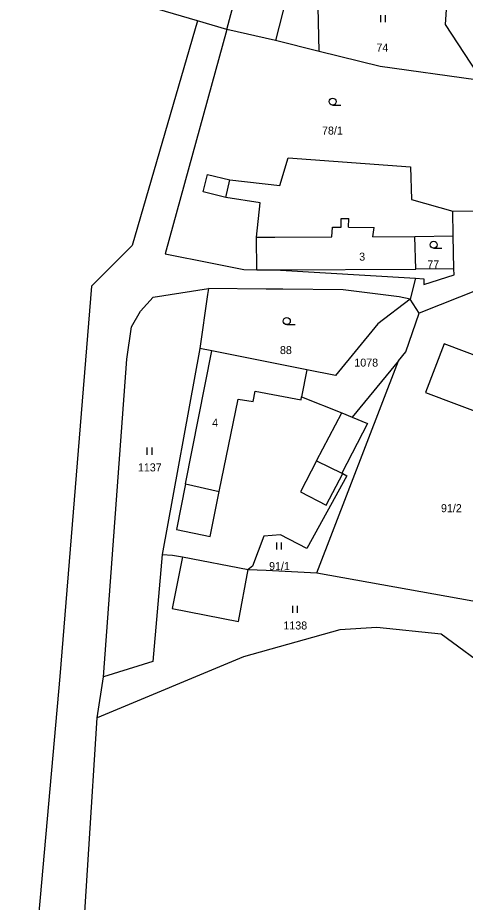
# Model space of a CAD drawing. Extents: x -746176 to -739709, y -1128407 to -1124482.
# Drawn here: x -742472.1 to -742377, y -1126240.2 to -1126052.3 of the extents above; entities that cross this region are included whole.
import ezdxf

# ---------------------------------------------------------------- set-up
doc = ezdxf.new("R2010")
doc.units = 0
for name, color, linetype in [('Hranice parcel', 7, 'Continuous'), ('Parcelní čísla', 7, 'Continuous'), ('Vnitřní kresba', 7, 'Continuous'), ('Značky kultur', 7, 'Continuous')]:
    doc.layers.add(name, color=color, linetype=linetype)

msp = doc.modelspace()

# ---------------------------------------------------------------- linework, layer by layer
at = {"layer": 'Hranice parcel'}
for p, q in [((-742410.68, -1126031.18), (-742417.35, -1126057.17)), ((-742433.87, -1126052.94), (-742452.02, -1126047.65)), ((-742427.68, -1126054.77), (-742433.87, -1126052.94)), ((-742417.35, -1126057.17), (-742427.68, -1126054.77)), ((-742408.01, -1126059.51), (-742417.35, -1126057.17)), ((-742379.56, -1126098.64), (-742379.6, -1126093.36)), ((-742379.39, -1126105.64), (-742379.56, -1126098.64)), ((-742387.54, -1126107.59), (-742388.7, -1126112.08)), ((-742386.77, -1126115.04), (-742388.7, -1126112.08)), ((-742389.6, -1126123.26), (-742386.77, -1126115.04)), ((-742433.38, -1126122.54), (-742441.38, -1126166.33)), ((-742391.19, -1126125.19), (-742389.6, -1126123.26)), ((-742408.55, -1126170.19), (-742391.19, -1126125.19)), ((-742391.19, -1126125.19), (-742401.05, -1126137.14)), ((-742408.55, -1126170.19), (-742366.28, -1126177.8)), ((-742455.22, -1126201.03), (-742453.88, -1126192.33))]:
    msp.add_line(p, q, dxfattribs=at)
for points in [[(-742427.68, -1126054.77), (-742421.67, -1126032.23), (-742472.11, -1126011.47)], [(-742408.01, -1126059.51), (-742408.36, -1126043.59), (-742380.73, -1126046.24)], [(-742380.73, -1126046.24), (-742381.25, -1126053.76), (-742374.55, -1126064.02)], [(-742433.87, -1126052.94), (-742447.8, -1126100.68), (-742456.41, -1126109.29), (-742463.16, -1126192.21), (-742472.54, -1126297.27), (-742476.24, -1126360.79), (-742482.39, -1126414.71)], [(-742427.68, -1126054.77), (-742440.74, -1126102.42), (-742430.76, -1126104.41), (-742424.03, -1126105.75), (-742421.29, -1126105.88)], [(-742374.74, -1126065.53), (-742395.07, -1126062.68), (-742408.01, -1126059.51)], [(-742421.29, -1126105.88), (-742421.35, -1126098.94), (-742420.61, -1126091.6), (-742427.91, -1126090.46), (-742432.7, -1126089.32), (-742431.8, -1126085.57), (-742427.02, -1126086.71), (-742416.37, -1126087.94), (-742414.61, -1126082.07), (-742388.6, -1126083.94), (-742388.43, -1126090.91), (-742379.6, -1126093.36)], [(-742379.6, -1126093.36), (-742370.19, -1126093.35), (-742362.62, -1126088.05), (-742361.35, -1126086.4)], [(-742379.39, -1126105.64), (-742387.46, -1126105.73), (-742387.67, -1126098.78), (-742379.56, -1126098.64)], [(-742421.29, -1126105.88), (-742418.62, -1126105.84), (-742417.46, -1126105.82), (-742387.54, -1126107.59)], [(-742387.54, -1126107.59), (-742385.77, -1126107.77), (-742385.76, -1126108.96), (-742379.36, -1126106.92), (-742379.39, -1126105.64)], [(-742453.88, -1126192.33), (-742448.94, -1126124.82), (-742447.92, -1126117.98), (-742446, -1126114.6), (-742443.31, -1126111.65), (-742431.56, -1126109.81)], [(-742431.56, -1126109.81), (-742431.74, -1126111.07), (-742433.38, -1126122.54)], [(-742388.7, -1126112.08), (-742391.06, -1126111.59), (-742402.96, -1126110.08), (-742415.74, -1126109.96), (-742419.27, -1126109.93), (-742431.56, -1126109.81)], [(-742351.14, -1126116.55), (-742365.05, -1126112.26), (-742373.77, -1126109.92), (-742386.77, -1126115.04)], [(-742388.7, -1126112.08), (-742395.57, -1126117.34), (-742404.55, -1126128.31), (-742410.69, -1126127.09)], [(-742410.69, -1126127.09), (-742430.85, -1126123.08), (-742433.38, -1126122.54)], [(-742360.61, -1126129.44), (-742370.56, -1126125.67), (-742369.93, -1126124), (-742372.74, -1126122.95), (-742373.37, -1126124.6), (-742381.46, -1126121.54), (-742385.41, -1126131.94), (-742364.54, -1126139.8), (-742360.61, -1126129.44)], [(-742410.69, -1126127.09), (-742411.76, -1126132.8), (-742403.21, -1126136.23), (-742401.05, -1126137.14)], [(-742401.05, -1126137.14), (-742397.77, -1126138.5), (-742403.21, -1126149.03), (-742402.98, -1126149.15), (-742402.18, -1126149.59), (-742410.69, -1126165.08), (-742416.29, -1126162.13), (-742419.8, -1126162.46), (-742422.21, -1126168.79), (-742423.12, -1126169.49)], [(-742441.38, -1126166.33), (-742443.37, -1126189.04), (-742453.88, -1126192.33)], [(-742441.38, -1126166.33), (-742439.21, -1126166.45), (-742437.12, -1126166.85), (-742439.28, -1126177.82), (-742425.2, -1126180.54), (-742423.12, -1126169.49)], [(-742423.12, -1126169.49), (-742419.32, -1126169.67), (-742408.55, -1126170.19)], [(-742371.13, -1126191.3), (-742382.1, -1126183.23), (-742395.78, -1126181.85), (-742403.65, -1126182.31), (-742424.12, -1126188.09), (-742455.22, -1126201.03)], [(-742521.95, -1126773.52), (-742504.56, -1126672.68), (-742497, -1126628.23), (-742488.98, -1126567.9), (-742478.35, -1126466.13), (-742467.6, -1126363.23), (-742463.32, -1126296.13), (-742459.73, -1126263.65), (-742452.82, -1126263.88), (-742450.23, -1126260.63), (-742452.38, -1126257.65), (-742458.75, -1126256.81), (-742455.22, -1126201.03)]]:
    msp.add_lwpolyline(points, dxfattribs=at)
at = {"layer": 'Vnitřní kresba'}
for p, q in [((-742427.91, -1126090.46), (-742427.02, -1126086.71)), ((-742403.39, -1126096.78), (-742403.37, -1126094.93)), ((-742403.37, -1126094.93), (-742401.75, -1126094.95)), ((-742401.77, -1126096.8), (-742401.75, -1126094.95)), ((-742405.37, -1126098.85), (-742405.22, -1126096.76)), ((-742405.22, -1126096.76), (-742403.39, -1126096.78)), ((-742401.77, -1126096.8), (-742396.32, -1126096.85)), ((-742396.62, -1126098.81), (-742396.32, -1126096.85)), ((-742421.35, -1126098.94), (-742417.44, -1126098.9)), ((-742417.44, -1126098.9), (-742405.37, -1126098.85)), ((-742396.62, -1126098.81), (-742387.67, -1126098.78)), ((-742417.46, -1126105.82), (-742387.46, -1126105.73)), ((-742436.45, -1126151.3), (-742430.85, -1126123.08)), ((-742422.1, -1126133.81), (-742421.67, -1126131.64)), ((-742421.67, -1126131.64), (-742411.89, -1126133.49)), ((-742429.26, -1126152.92), (-742425.23, -1126133.31)), ((-742425.23, -1126133.31), (-742422.1, -1126133.81)), ((-742411.89, -1126133.49), (-742411.76, -1126132.8)), ((-742408.58, -1126146.46), (-742403.21, -1126136.23)), ((-742408.58, -1126146.46), (-742411.97, -1126153.04)), ((-742408.58, -1126146.46), (-742403.21, -1126149.03)), ((-742406.52, -1126155.83), (-742402.98, -1126149.15)), ((-742436.45, -1126151.3), (-742438.39, -1126161)), ((-742436.45, -1126151.3), (-742429.26, -1126152.92)), ((-742431.21, -1126162.5), (-742429.26, -1126152.92)), ((-742411.97, -1126153.04), (-742406.52, -1126155.83)), ((-742438.39, -1126161), (-742431.21, -1126162.5)), ((-742437.12, -1126166.85), (-742423.12, -1126169.49))]:
    msp.add_line(p, q, dxfattribs=at)
at = {"layer": 'Značky kultur'}
for p, q in [((-742394.93, -1126053.24), (-742394.93, -1126051.74)), ((-742393.93, -1126053.24), (-742393.93, -1126051.74)), ((-742405.18, -1126070.87), (-742403.43, -1126070.87)), ((-742383.7, -1126101.27), (-742381.95, -1126101.27)), ((-742414.92, -1126117.5), (-742413.17, -1126117.5)), ((-742444.57, -1126145.12), (-742444.57, -1126143.62)), ((-742443.57, -1126145.12), (-742443.57, -1126143.62)), ((-742417.04, -1126165.29), (-742417.04, -1126163.79)), ((-742416.04, -1126165.29), (-742416.04, -1126163.79)), ((-742413.64, -1126178.7), (-742413.64, -1126177.2)), ((-742412.64, -1126178.7), (-742412.64, -1126177.2))]:
    msp.add_line(p, q, dxfattribs=at)
for centre in [(-742405.18, -1126070.12), (-742383.7, -1126100.52), (-742414.92, -1126116.75)]:
    msp.add_circle(centre, 0.75, dxfattribs=at)

# ---------------------------------------------------------------- texts
at = {"layer": 'Parcelní čísla'}
for s, p in [('74', (-742395.86, -1126059.49)), ('78/1', (-742407.43, -1126077.12)), ('3', (-742399.53, -1126103.9)), ('77', (-742385.04, -1126105.53)), ('88', (-742416.37, -1126123.75)), ('1078', (-742400.56, -1126126.41)), ('4', (-742430.78, -1126139.17)), ('1137', (-742446.57, -1126148.67)), ('91/2', (-742382.14, -1126157.33)), ('91/1', (-742418.68, -1126169.63)), ('1138', (-742415.64, -1126182.25))]:
    msp.add_text(s, height=1.7, dxfattribs=at).set_placement(p)

doc.saveas('drawing.dxf')
